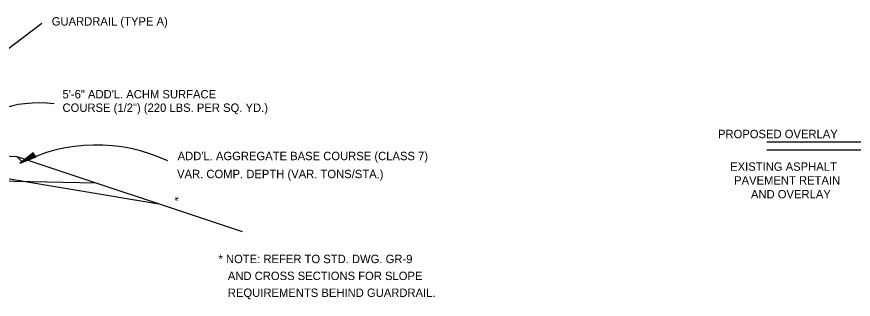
# Model space of a CAD drawing. Extents: x 1955771 to 1955918, y 566326 to 566544.
# Drawn here: x 1955804.2 to 1955864, y 566510.1 to 566530.3 of the extents above; entities that cross this region are included whole.
import ezdxf

# ---------------------------------------------------------------- set-up
doc = ezdxf.new("R2010")
doc.units = 0
doc.layers.add('Default', color=7, linetype='Continuous')

msp = doc.modelspace()

# ---------------------------------------------------------------- linework, layer by layer
at = {"layer": 'Default'}
for p, q in [((1955799.136, 566524.648), (1955805.982, 566529.821)), ((1955857.796, 566521.353), (1955869.343, 566521.353)), ((1955790.882, 566520.843), (1955804.181, 566520.31)), ((1955790.882, 566520.843), (1955814.346, 566516.93)), ((1955805.352, 566520.57), (1955804.39, 566519.803)), ((1955805.369, 566520.541), (1955804.567, 566519.902)), ((1955805.384, 566520.515), (1955804.747, 566520.009)), ((1955805.537, 566520.252), (1955805.352, 566520.57)), ((1955857.796, 566520.776), (1955910.499, 566520.776)), ((1955804.181, 566520.31), (1955820.292, 566514.955)), ((1955804.181, 566520.31), (1955804.599, 566519.895)), ((1955805.537, 566520.252), (1955804.39, 566519.803)), ((1955805.52, 566520.279), (1955804.567, 566519.902)), ((1955805.503, 566520.306), (1955804.747, 566520.009)), ((1955805.399, 566520.49), (1955804.922, 566520.111)), ((1955805.488, 566520.33), (1955804.922, 566520.111)), ((1955805.413, 566520.461), (1955805.1, 566520.213)), ((1955805.474, 566520.357), (1955805.1, 566520.213)), ((1955805.43, 566520.434), (1955805.279, 566520.315)), ((1955805.459, 566520.386), (1955805.279, 566520.315)), ((1955771.003, 566519.197), (1955809.855, 566518.425))]:
    msp.add_line(p, q, dxfattribs=at)
msp.add_arc((1955809.873, 566509.103), 12.021, 64.88758, 117.13783, dxfattribs=at)
msp.add_ellipse((1955806.375, 566520.125), major_axis=(-6.005, 0.733), ratio=0.655798, start_param=4.712389, end_param=6.093533, dxfattribs=at)

# ---------------------------------------------------------------- texts
for s, p in [('GUARDRAIL (TYPE A)', (1955806.682, 566529.654)), ('5\'-6" ADD\'L. ACHM SURFACE ', (1955807.45, 566524.452)), ('COURSE (1/2") (220 LBS. PER SQ. YD.)', (1955807.45, 566523.488)), ('PROPOSED OVERLAY', (1955854.3, 566521.61)), ("ADD'L. AGGREGATE BASE COURSE (CLASS 7)", (1955815.678, 566520.039)), ('VAR. COMP. DEPTH (VAR. TONS/STA.)', (1955815.638, 566518.754)), ('EXISTING ASPHALT', (1955855.169, 566519.283)), ('PAVEMENT RETAIN', (1955855.452, 566518.297)), ('AND OVERLAY', (1955856.656, 566517.311)), ('* NOTE: REFER TO STD. DWG. GR-9', (1955818.599, 566512.684)), ('   AND CROSS SECTIONS FOR SLOPE', (1955818.599, 566511.476)), ('   REQUIREMENTS BEHIND GUARDRAIL.', (1955818.599, 566510.269))]:
    msp.add_text(s, height=0.6, dxfattribs=at).set_placement(p)
msp.add_text('*', height=0.6, rotation=341.65133, dxfattribs=at).set_placement((1955815.325, 566516.911))

doc.saveas('drawing.dxf')
